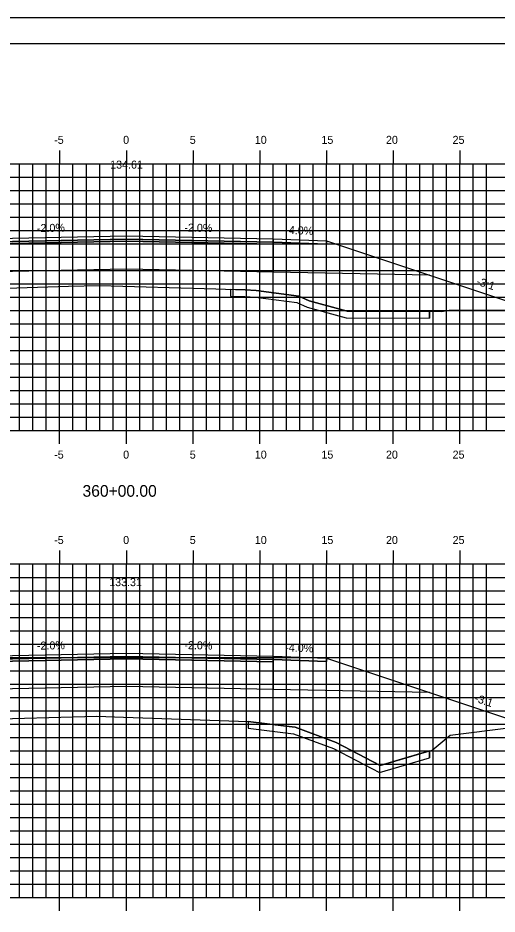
# Model space of a CAD drawing. Extents: x 1146303 to 1146473, y 608981 to 609091.
# Drawn here: x 1146377.8 to 1146413.7, y 609024.1 to 609091.3 of the extents above; entities that cross this region are included whole.
import ezdxf

# ---------------------------------------------------------------- set-up
doc = ezdxf.new("R2010")
doc.units = 0
for name, color, linetype in [('ANNOTATION', 7, 'Continuous'), ('BORDER', 7, 'Continuous'), ('D_Roadway_Centerline', 7, 'Continuous'), ('D_Roadway_Centerline_Text', 7, 'Continuous'), ('D_Roadway_Edge_Shoulder', 7, 'Continuous'), ('D_Roadway_Edge_TW', 7, 'Continuous'), ('D_Roadway_Pavement', 7, 'Continuous'), ('D_Roadway_SlopeLines', 7, 'Continuous'), ('D_Roadway_SubGrade', 7, 'Continuous'), ('H_V ANNOTATION', 7, 'Continuous'), ('MAJOR', 7, 'Continuous'), ('MINOR', 7, 'Continuous'), ('PLOT BOUNDARY', 7, 'Continuous'), ('S_Roadway_Centerline', 7, 'Continuous'), ('SHADING', 7, 'Continuous')]:
    doc.layers.add(name, color=color, linetype=linetype)

msp = doc.modelspace()

# ---------------------------------------------------------------- linework, layer by layer
for points in [[(1146345.732, 609068.815), (1146351.756, 609070.823), (1146354.756, 609071.823), (1146361.905, 609074.206), (1146361.906, 609074.206), (1146374.915, 609074.726), (1146385.915, 609074.946), (1146396.915, 609074.726), (1146400.915, 609074.566), (1146408.638, 609071.992), (1146411.638, 609070.992), (1146416.264, 609069.45)], [(1146344.176, 609035.23), (1146357.382, 609039.632), (1146360.382, 609040.632), (1146367.914, 609043.143), (1146367.915, 609043.143), (1146374.915, 609043.423), (1146385.915, 609043.643), (1146396.915, 609043.423), (1146400.915, 609043.263), (1146408.638, 609040.689), (1146411.638, 609039.689), (1146415.984, 609038.24)]]:
    msp.add_lwpolyline(points)
at = {"layer": 'BORDER'}
msp.add_lwpolyline([(1146310.915, 608984.335), (1146470.915, 608984.335), (1146470.915, 609089.335), (1146310.915, 609089.335)], close=True, dxfattribs=at)
at = {"layer": 'D_Roadway_Edge_Shoulder'}
for points in [[(1146396.915, 609074.726), (1146400.915, 609074.566), (1146400.915, 609074.316), (1146396.915, 609074.476)], [(1146396.915, 609043.423), (1146400.915, 609043.263), (1146400.915, 609043.013), (1146396.915, 609043.173)]]:
    msp.add_lwpolyline(points, close=True, dxfattribs=at)
at = {"layer": 'D_Roadway_Edge_TW'}
for points in [[(1146374.915, 609074.476), (1146374.915, 609074.726), (1146385.915, 609074.946), (1146396.915, 609074.726), (1146396.915, 609074.476), (1146385.915, 609074.696)], [(1146374.915, 609043.173), (1146374.915, 609043.423), (1146385.915, 609043.643), (1146396.915, 609043.423), (1146396.915, 609043.173), (1146385.915, 609043.393)]]:
    msp.add_lwpolyline(points, close=True, dxfattribs=at)
at = {"layer": 'D_Roadway_Pavement'}
for points in [[(1146374.915, 609074.31), (1146374.915, 609074.476), (1146385.915, 609074.696), (1146396.915, 609074.476), (1146396.915, 609074.31), (1146385.915, 609074.53)], [(1146374.915, 609043.006), (1146374.915, 609043.173), (1146385.915, 609043.393), (1146396.915, 609043.173), (1146396.915, 609043.007), (1146385.915, 609043.227)]]:
    msp.add_lwpolyline(points, close=True, dxfattribs=at)
at = {"layer": 'D_Roadway_SlopeLines'}
for points in [[(1146408.638, 609071.992), (1146411.638, 609070.992)], [(1146411.638, 609070.992), (1146416.264, 609069.45)], [(1146408.638, 609040.689), (1146411.638, 609039.689)], [(1146411.638, 609039.689), (1146415.984, 609038.24)]]:
    msp.add_lwpolyline(points, dxfattribs=at)
at = {"layer": 'D_Roadway_SubGrade'}
for p, q in [((1146393.718, 609070.927), (1146393.718, 609070.427)), ((1146408.638, 609069.266), (1146408.638, 609068.766)), ((1146395.034, 609038.539), (1146395.034, 609038.039)), ((1146408.638, 609036.331), (1146408.638, 609035.811))]:
    msp.add_line(p, q, dxfattribs=at)
for points in [[(1146374.915, 609072.226), (1146374.915, 609074.31), (1146385.915, 609074.53), (1146396.915, 609074.31), (1146396.915, 609072.226), (1146385.915, 609072.446)], [(1146396.915, 609074.31), (1146396.915, 609074.476), (1146400.915, 609074.316), (1146400.915, 609074.566), (1146400.915, 609074.566), (1146408.638, 609071.992), (1146396.915, 609072.226)], [(1146374.915, 609040.923), (1146374.915, 609043.006), (1146385.915, 609043.227), (1146396.915, 609043.007), (1146396.915, 609040.923), (1146385.915, 609041.143)], [(1146396.915, 609043.007), (1146396.915, 609043.173), (1146400.915, 609043.013), (1146400.915, 609043.263), (1146400.915, 609043.263), (1146408.638, 609040.689), (1146396.915, 609040.923)]]:
    msp.add_lwpolyline(points, close=True, dxfattribs=at)
for points in [[(1146393.718, 609070.427), (1146394.804, 609070.39), (1146395.584, 609070.335), (1146398.699, 609069.932), (1146399.454, 609069.59), (1146402.392, 609068.78), (1146408.638, 609068.766)], [(1146395.034, 609038.036), (1146397.834, 609037.683), (1146398.451, 609037.609), (1146401.428, 609036.5), (1146404.895, 609034.702), (1146408.638, 609035.811)]]:
    msp.add_lwpolyline(points, dxfattribs=at)
at = {"layer": 'MAJOR'}
for p, q in [((1146380.915, 609081.337), (1146380.915, 609080.335)), ((1146385.915, 609081.337), (1146385.915, 609080.335)), ((1146390.915, 609081.337), (1146390.915, 609080.335)), ((1146395.915, 609081.337), (1146395.915, 609080.335)), ((1146400.915, 609081.337), (1146400.915, 609080.335)), ((1146405.915, 609081.337), (1146405.915, 609080.335)), ((1146410.915, 609081.337), (1146410.915, 609080.335)), ((1146315.915, 609080.335), (1146455.915, 609080.335)), ((1146315.915, 609080.335), (1146455.915, 609080.335)), ((1146380.915, 609060.335), (1146380.915, 609080.335)), ((1146385.915, 609060.335), (1146385.915, 609080.335)), ((1146390.915, 609060.335), (1146390.915, 609080.335)), ((1146395.915, 609060.335), (1146395.915, 609080.335)), ((1146400.915, 609060.335), (1146400.915, 609080.335)), ((1146405.915, 609060.335), (1146405.915, 609080.335)), ((1146410.915, 609060.335), (1146410.915, 609080.335)), ((1146315.915, 609075.335), (1146455.915, 609075.335)), ((1146315.915, 609070.335), (1146455.915, 609070.335)), ((1146315.915, 609065.335), (1146455.915, 609065.335)), ((1146315.915, 609060.335), (1146455.915, 609060.335)), ((1146315.915, 609060.335), (1146455.915, 609060.335)), ((1146380.915, 609059.333), (1146380.915, 609060.335)), ((1146385.915, 609059.333), (1146385.915, 609060.335)), ((1146390.915, 609059.333), (1146390.915, 609060.335)), ((1146395.915, 609059.333), (1146395.915, 609060.335)), ((1146400.915, 609059.333), (1146400.915, 609060.335)), ((1146405.915, 609059.333), (1146405.915, 609060.335)), ((1146410.915, 609059.333), (1146410.915, 609060.335)), ((1146380.915, 609051.337), (1146380.915, 609050.335)), ((1146385.915, 609051.337), (1146385.915, 609050.335)), ((1146390.915, 609051.337), (1146390.915, 609050.335)), ((1146395.915, 609051.337), (1146395.915, 609050.335)), ((1146400.915, 609051.337), (1146400.915, 609050.335)), ((1146405.915, 609051.337), (1146405.915, 609050.335)), ((1146410.915, 609051.337), (1146410.915, 609050.335)), ((1146315.915, 609050.335), (1146455.915, 609050.335)), ((1146315.915, 609050.335), (1146455.915, 609050.335)), ((1146380.915, 609025.335), (1146380.915, 609050.335)), ((1146385.915, 609025.335), (1146385.915, 609050.335)), ((1146390.915, 609025.335), (1146390.915, 609050.335)), ((1146395.915, 609025.335), (1146395.915, 609050.335)), ((1146400.915, 609025.335), (1146400.915, 609050.335)), ((1146405.915, 609025.335), (1146405.915, 609050.335)), ((1146410.915, 609025.335), (1146410.915, 609050.335)), ((1146315.915, 609045.335), (1146455.915, 609045.335)), ((1146315.915, 609040.335), (1146455.915, 609040.335)), ((1146315.915, 609035.335), (1146455.915, 609035.335)), ((1146315.915, 609030.335), (1146455.915, 609030.335)), ((1146315.915, 609025.335), (1146455.915, 609025.335)), ((1146315.915, 609025.335), (1146455.915, 609025.335)), ((1146380.915, 609024.333), (1146380.915, 609025.335)), ((1146385.915, 609024.333), (1146385.915, 609025.335)), ((1146390.915, 609024.333), (1146390.915, 609025.335)), ((1146395.915, 609024.333), (1146395.915, 609025.335)), ((1146400.915, 609024.333), (1146400.915, 609025.335)), ((1146405.915, 609024.333), (1146405.915, 609025.335)), ((1146410.915, 609024.333), (1146410.915, 609025.335))]:
    msp.add_line(p, q, dxfattribs=at)
at = {"layer": 'MINOR'}
for p, q in [((1146377.915, 609060.335), (1146377.915, 609080.335)), ((1146378.915, 609060.335), (1146378.915, 609080.335)), ((1146379.915, 609060.335), (1146379.915, 609080.335)), ((1146381.915, 609060.335), (1146381.915, 609080.335)), ((1146382.915, 609060.335), (1146382.915, 609080.335)), ((1146383.915, 609060.335), (1146383.915, 609080.335)), ((1146384.915, 609060.335), (1146384.915, 609080.335)), ((1146386.915, 609060.335), (1146386.915, 609080.335)), ((1146387.915, 609060.335), (1146387.915, 609080.335)), ((1146388.915, 609060.335), (1146388.915, 609080.335)), ((1146389.915, 609060.335), (1146389.915, 609080.335)), ((1146391.915, 609060.335), (1146391.915, 609080.335)), ((1146392.915, 609060.335), (1146392.915, 609080.335)), ((1146393.915, 609060.335), (1146393.915, 609080.335)), ((1146394.915, 609060.335), (1146394.915, 609080.335)), ((1146396.915, 609060.335), (1146396.915, 609080.335)), ((1146397.915, 609060.335), (1146397.915, 609080.335)), ((1146398.915, 609060.335), (1146398.915, 609080.335)), ((1146399.915, 609060.335), (1146399.915, 609080.335)), ((1146401.915, 609060.335), (1146401.915, 609080.335)), ((1146402.915, 609060.335), (1146402.915, 609080.335)), ((1146403.915, 609060.335), (1146403.915, 609080.335)), ((1146404.915, 609060.335), (1146404.915, 609080.335)), ((1146406.915, 609060.335), (1146406.915, 609080.335)), ((1146407.915, 609060.335), (1146407.915, 609080.335)), ((1146408.915, 609060.335), (1146408.915, 609080.335)), ((1146409.915, 609060.335), (1146409.915, 609080.335)), ((1146411.915, 609060.335), (1146411.915, 609080.335)), ((1146412.915, 609060.335), (1146412.915, 609080.335)), ((1146315.915, 609079.335), (1146455.915, 609079.335)), ((1146315.915, 609078.335), (1146455.915, 609078.335)), ((1146315.915, 609077.335), (1146455.915, 609077.335)), ((1146315.915, 609076.335), (1146455.915, 609076.335)), ((1146315.915, 609074.335), (1146455.915, 609074.335)), ((1146315.915, 609073.335), (1146455.915, 609073.335)), ((1146315.915, 609072.335), (1146455.915, 609072.335)), ((1146315.915, 609071.335), (1146455.915, 609071.335)), ((1146315.915, 609069.335), (1146455.915, 609069.335)), ((1146315.915, 609068.335), (1146455.915, 609068.335)), ((1146315.915, 609067.335), (1146455.915, 609067.335)), ((1146315.915, 609066.335), (1146455.915, 609066.335)), ((1146315.915, 609064.335), (1146455.915, 609064.335)), ((1146315.915, 609063.335), (1146455.915, 609063.335)), ((1146315.915, 609062.335), (1146455.915, 609062.335)), ((1146315.915, 609061.335), (1146455.915, 609061.335)), ((1146377.915, 609025.335), (1146377.915, 609050.335)), ((1146378.915, 609025.335), (1146378.915, 609050.335)), ((1146379.915, 609025.335), (1146379.915, 609050.335)), ((1146381.915, 609025.335), (1146381.915, 609050.335)), ((1146382.915, 609025.335), (1146382.915, 609050.335)), ((1146383.915, 609025.335), (1146383.915, 609050.335)), ((1146384.915, 609025.335), (1146384.915, 609050.335)), ((1146386.915, 609025.335), (1146386.915, 609050.335)), ((1146387.915, 609025.335), (1146387.915, 609050.335)), ((1146388.915, 609025.335), (1146388.915, 609050.335)), ((1146389.915, 609025.335), (1146389.915, 609050.335)), ((1146391.915, 609025.335), (1146391.915, 609050.335)), ((1146392.915, 609025.335), (1146392.915, 609050.335)), ((1146393.915, 609025.335), (1146393.915, 609050.335)), ((1146394.915, 609025.335), (1146394.915, 609050.335)), ((1146396.915, 609025.335), (1146396.915, 609050.335)), ((1146397.915, 609025.335), (1146397.915, 609050.335)), ((1146398.915, 609025.335), (1146398.915, 609050.335)), ((1146399.915, 609025.335), (1146399.915, 609050.335)), ((1146401.915, 609025.335), (1146401.915, 609050.335)), ((1146402.915, 609025.335), (1146402.915, 609050.335)), ((1146403.915, 609025.335), (1146403.915, 609050.335)), ((1146404.915, 609025.335), (1146404.915, 609050.335)), ((1146406.915, 609025.335), (1146406.915, 609050.335)), ((1146407.915, 609025.335), (1146407.915, 609050.335)), ((1146408.915, 609025.335), (1146408.915, 609050.335)), ((1146409.915, 609025.335), (1146409.915, 609050.335)), ((1146411.915, 609025.335), (1146411.915, 609050.335)), ((1146412.915, 609025.335), (1146412.915, 609050.335)), ((1146315.915, 609049.335), (1146455.915, 609049.335)), ((1146315.915, 609048.335), (1146455.915, 609048.335)), ((1146315.915, 609047.335), (1146455.915, 609047.335)), ((1146315.915, 609046.335), (1146455.915, 609046.335)), ((1146315.915, 609044.335), (1146455.915, 609044.335)), ((1146315.915, 609043.335), (1146455.915, 609043.335)), ((1146315.915, 609042.335), (1146455.915, 609042.335)), ((1146315.915, 609041.335), (1146455.915, 609041.335)), ((1146315.915, 609039.335), (1146455.915, 609039.335)), ((1146315.915, 609038.335), (1146455.915, 609038.335)), ((1146315.915, 609037.335), (1146455.915, 609037.335)), ((1146315.915, 609036.335), (1146455.915, 609036.335)), ((1146315.915, 609034.335), (1146455.915, 609034.335)), ((1146315.915, 609033.335), (1146455.915, 609033.335)), ((1146315.915, 609032.335), (1146455.915, 609032.335)), ((1146315.915, 609031.335), (1146455.915, 609031.335)), ((1146315.915, 609029.335), (1146455.915, 609029.335)), ((1146315.915, 609028.335), (1146455.915, 609028.335)), ((1146315.915, 609027.335), (1146455.915, 609027.335)), ((1146315.915, 609026.335), (1146455.915, 609026.335))]:
    msp.add_line(p, q, dxfattribs=at)
at = {"layer": 'PLOT BOUNDARY'}
msp.add_lwpolyline([(1146302.822, 608981.276), (1146472.822, 608981.276), (1146472.822, 609091.276), (1146302.822, 609091.276)], close=True, dxfattribs=at)
at = {"layer": 'S_Roadway_Centerline'}
for points in [[(1146335.721, 609068.741), (1146341.913, 609068.95), (1146350.501, 609068.647), (1146356.167, 609069.121), (1146361.353, 609069.451), (1146366.347, 609070.038), (1146369.93, 609070.733), (1146371.977, 609070.829), (1146373.05, 609070.897), (1146381.577, 609071.163), (1146383.909, 609071.217), (1146392.607, 609070.964), (1146394.83, 609070.89), (1146395.634, 609070.833), (1146398.837, 609070.419), (1146399.625, 609070.062), (1146402.46, 609069.28), (1146409.532, 609069.264), (1146410.109, 609069.369), (1146413.555, 609069.372), (1146429.262, 609069.823), (1146435.475, 609069.99)], [(1146333.388, 609034.911), (1146346.209, 609035.291), (1146349.129, 609035.414), (1146357.59, 609036.333), (1146359.818, 609036.527), (1146361.268, 609036.808), (1146369.098, 609038.216), (1146370.961, 609038.37), (1146372.738, 609038.608), (1146374.647, 609038.666), (1146383.693, 609038.936), (1146385.688, 609038.859), (1146395.034, 609038.539), (1146397.895, 609038.178), (1146398.57, 609038.098), (1146401.631, 609036.957), (1146404.946, 609035.238), (1146408.835, 609036.389), (1146410.172, 609037.511), (1146433.848, 609040.479), (1146437.527, 609040.851)]]:
    msp.add_lwpolyline(points, dxfattribs=at)
at = {"layer": 'SHADING'}
for p, q in [((1146393.718, 609070.927), (1146393.718, 609070.427)), ((1146408.638, 609069.266), (1146402.46, 609069.28)), ((1146408.638, 609068.766), (1146408.638, 609069.266)), ((1146395.034, 609038.539), (1146395.034, 609038.039)), ((1146408.638, 609035.811), (1146408.638, 609036.331))]:
    msp.add_line(p, q, dxfattribs=at)
for points in [[(1146402.46, 609069.28), (1146399.625, 609070.062), (1146398.837, 609070.419), (1146395.634, 609070.833), (1146394.83, 609070.89), (1146393.718, 609070.927)], [(1146393.718, 609070.427), (1146394.804, 609070.39), (1146395.584, 609070.335), (1146398.699, 609069.932), (1146399.454, 609069.59), (1146402.392, 609068.78), (1146408.638, 609068.766)], [(1146408.638, 609036.331), (1146404.946, 609035.238), (1146401.631, 609036.957), (1146398.57, 609038.098), (1146397.895, 609038.178), (1146395.034, 609038.539)], [(1146395.034, 609038.039), (1146397.834, 609037.683), (1146398.451, 609037.609), (1146401.428, 609036.5), (1146404.895, 609034.702), (1146408.638, 609035.811)]]:
    msp.add_lwpolyline(points, dxfattribs=at)

# ---------------------------------------------------------------- texts
at = {"layer": 'ANNOTATION'}
for s, rotation, p in [('-2.0%', 1.14576, (1146379.218, 609075.213)), ('-2.0%', 358.85424, (1146390.258, 609075.26)), ('-4.0%', 357.70939, (1146397.811, 609075.091)), ('-3:1', 341.56505, (1146412.101, 609071.292)), ('-2.0%', 1.14576, (1146379.218, 609043.909)), ('-2.0%', 358.85424, (1146390.258, 609043.957)), ('-4.0%', 357.70939, (1146397.811, 609043.788)), ('-3:1', 341.56505, (1146411.961, 609040.035))]:
    msp.add_text(s, height=0.6, rotation=rotation, dxfattribs=at).set_placement(p)
at = {"layer": 'D_Roadway_Centerline'}
for s, p in [('C', (1146385.909, 609074.946)), ('L', (1146385.915, 609074.939)), ('C', (1146385.909, 609043.643)), ('L', (1146385.915, 609043.636))]:
    msp.add_text(s, height=0.0146, dxfattribs=at).set_placement(p)
at = {"layer": 'D_Roadway_Centerline_Text'}
for s, p in [('134.61', (1146384.7, 609079.978)), ('133.31', (1146384.625, 609048.675))]:
    msp.add_text(s, height=0.6, dxfattribs=at).set_placement(p)
at = {"layer": 'H_V ANNOTATION'}
for s, height, p in [('-5', 0.6, (1146380.505, 609081.835)), ('0', 0.6, (1146385.674, 609081.835)), ('5', 0.6, (1146390.666, 609081.835)), ('10', 0.6, (1146395.54, 609081.835)), ('15', 0.6, (1146400.532, 609081.835)), ('20', 0.6, (1146405.369, 609081.835)), ('25', 0.6, (1146410.361, 609081.835)), ('-5', 0.6, (1146380.505, 609058.235)), ('0', 0.6, (1146385.674, 609058.235)), ('5', 0.6, (1146390.666, 609058.235)), ('10', 0.6, (1146395.54, 609058.235)), ('15', 0.6, (1146400.532, 609058.235)), ('20', 0.6, (1146405.369, 609058.235)), ('25', 0.6, (1146410.361, 609058.235)), ('360+00.00', 0.875, (1146382.63, 609055.378)), ('-5', 0.6, (1146380.505, 609051.835)), ('0', 0.6, (1146385.674, 609051.835)), ('5', 0.6, (1146390.666, 609051.835)), ('10', 0.6, (1146395.54, 609051.835)), ('15', 0.6, (1146400.532, 609051.835)), ('20', 0.6, (1146405.369, 609051.835)), ('25', 0.6, (1146410.361, 609051.835))]:
    msp.add_text(s, height=height, dxfattribs=at).set_placement(p)
at = {"layer": 'S_Roadway_Centerline'}
for s, p in [('L', (1146383.9, 609071.209)), ('C', (1146383.904, 609071.217)), ('L', (1146383.684, 609038.929)), ('C', (1146383.687, 609038.936))]:
    msp.add_text(s, height=0.0146, dxfattribs=at).set_placement(p)

doc.saveas('drawing.dxf')
